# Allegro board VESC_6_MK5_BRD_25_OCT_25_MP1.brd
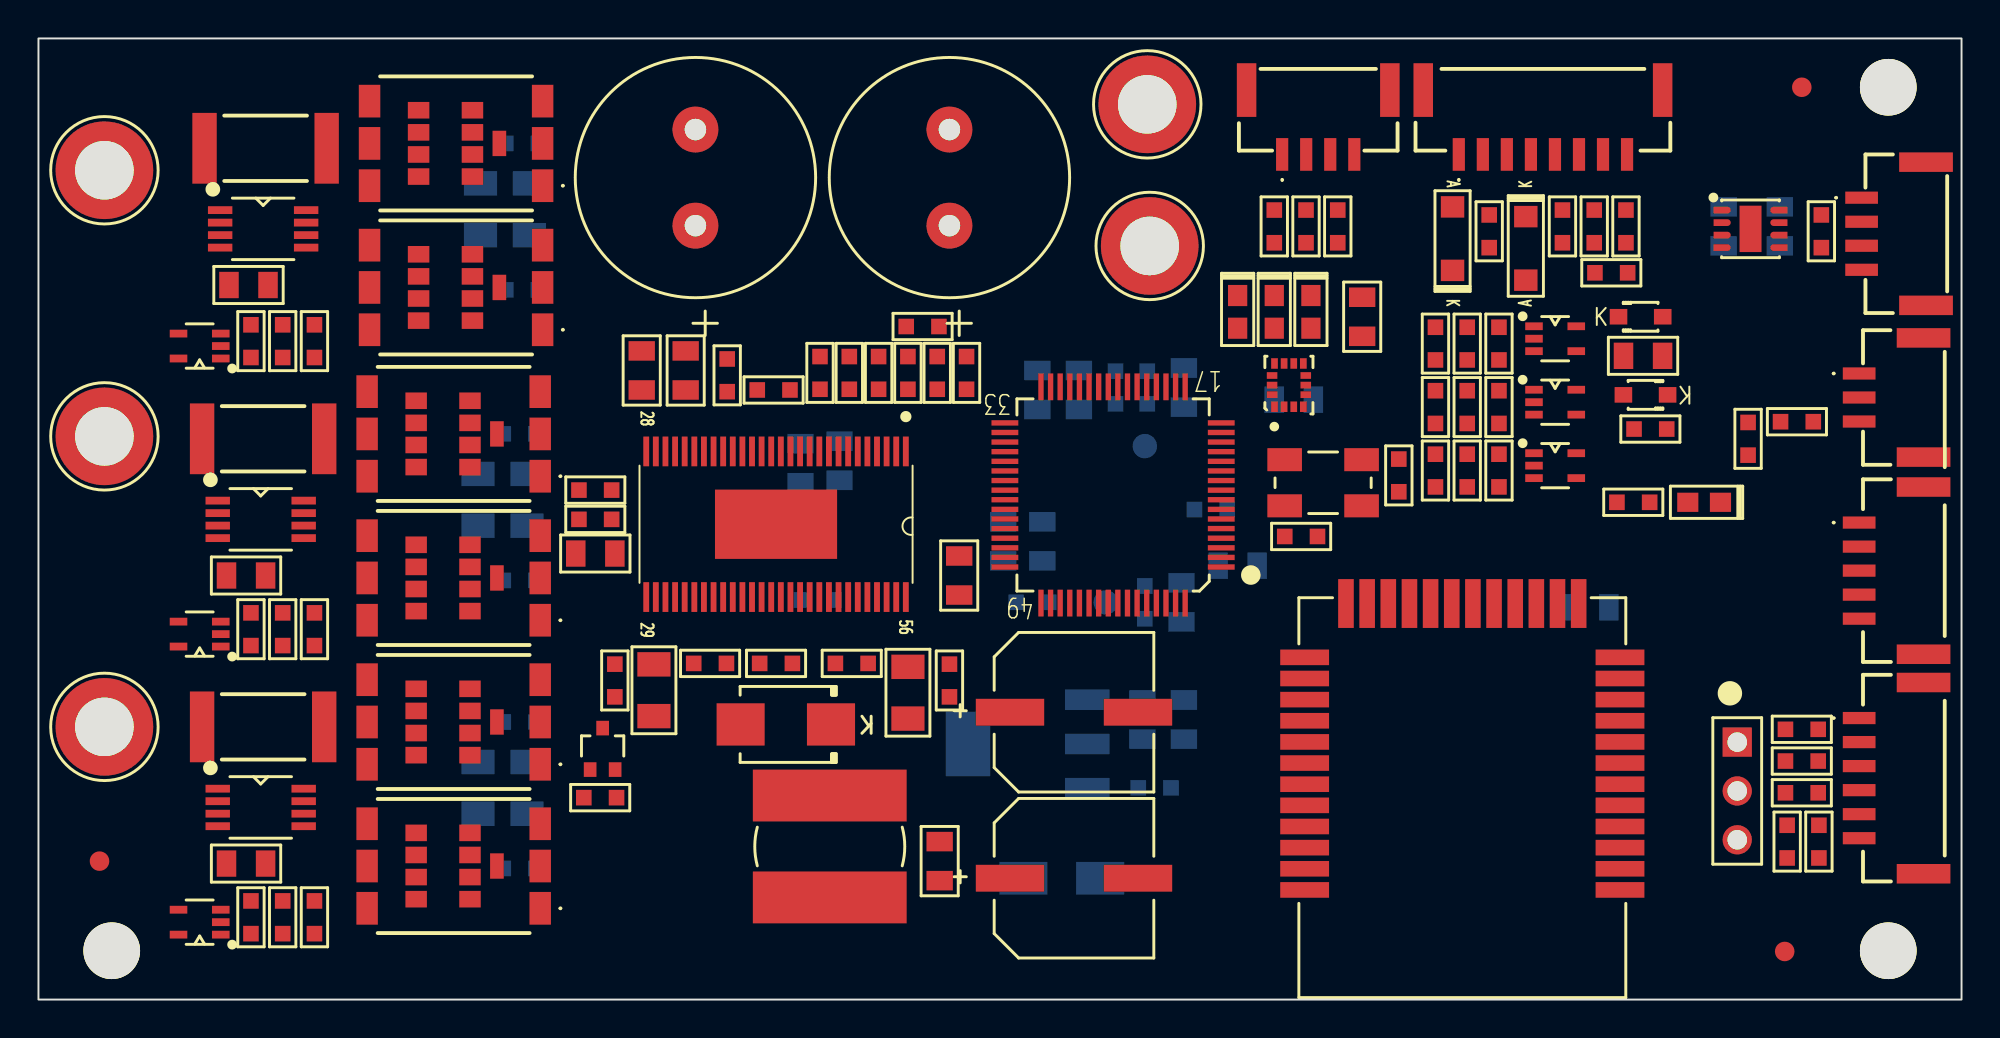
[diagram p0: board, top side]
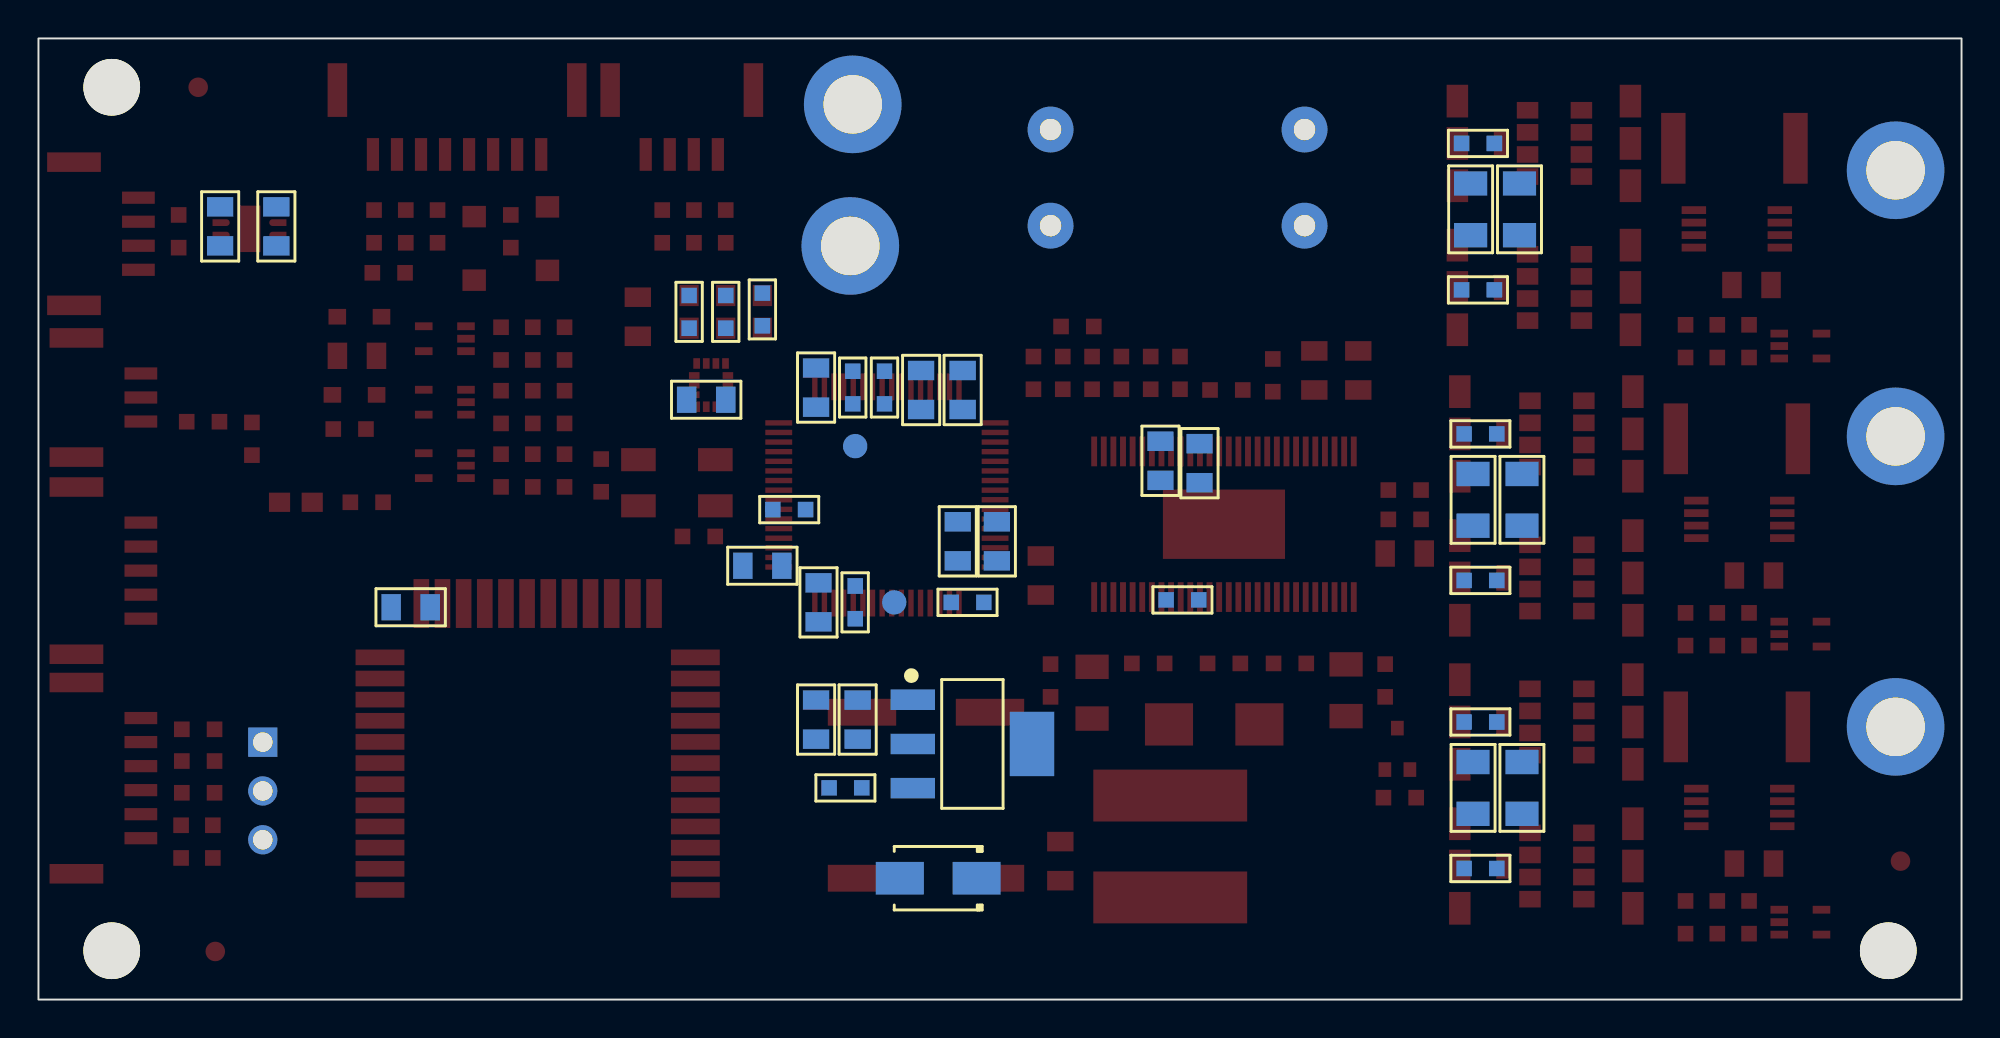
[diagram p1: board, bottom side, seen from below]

Outline 100 x 50 mm; copper layers: TOP, BOTTOM. Coordinates in mm from the lower left corner of the outline.
Outline path: rectangle 0,0 100,50

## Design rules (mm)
constraint set DEFAULT: min track width 0.203

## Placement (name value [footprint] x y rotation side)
C1  2.2uF  [0805]  83.44 33.49 0 top
C2  100nF  [0603]  79.25 40.22 90 top
C3  100nF  [0603]  92.58 8.22 270 top
C4  100nF  [0603]  88.9 29.17 90 top
C5  2.2uF  [0805]  68.83 35.52 90 top
C6  2.2uF  [0805]  65.28 31.2 180 bottom
C7  2.2uF  [0805]  90.55 40.22 90 bottom
C8  2.2uF  [0805]  87.63 40.22 90 bottom
C9  2.2uF  [0805]  80.65 20.41 180 bottom
C10  6.8nF  [0603]  45.97 35.01 0 top
C11  120pF  [0603]  46.74 32.6 90 top
C12  15nF  [0603]  47.37 16.6 90 top
C13  4.7uF_100V  [1206]  45.21 15.96 90 top
C14  100nF  [0603]  42.29 17.49 0 top
C15  220nF  [0603]  40.51 20.79 180 bottom
C16  2.2uF  [0805]  46.86 7.2 90 top
C17  47uF  [CAP_8X10]  53.85 14.95 0 top
C18  47uF  [CAP_8X10]  53.85 6.31 0 top
C19  22nF  [0603]  38.23 31.71 0 top
C20  220nF  [0603]  38.35 17.49 180 top
C21  2.2uF  [0805]  39.62 27.9 90 bottom
C22  2.2uF  [0805]  41.66 28.03 90 bottom
C23  220nF  [0603]  34.92 17.49 180 top
C24  2.2uF  [0805]  33.66 32.73 270 top
C25  2.2uF  [0805]  31.37 32.73 270 top
C26  4.7uF_100V  [1206]  32 16.09 90 top
C27  100nF  [0603]  75.95 27.52 90 top
C28  100nF  [0603]  75.95 30.82 90 top
C29  100nF  [0603]  75.95 34.13 90 top
C30  2.2u  [0603]  58.04 11.01 180 bottom
C31  2.2uF  [0805]  57.4 14.57 270 bottom
C32  2.2uF  [0805]  59.56 14.57 270 bottom
C33  4.7uF_100V  [1206]  22.99 41.11 90 bottom
C34  4.7uF_100V  [1206]  25.53 41.11 90 bottom
C35  4.7uF_100V  [1206]  22.86 26 90 bottom
C36  4.7uF_100V  [1206]  25.4 26 90 bottom
C37  4.7uF_100V  [1206]  25.4 11.01 90 bottom
C38  4.7uF_100V  [1206]  22.86 11.01 90 bottom
C39  2.2uF  [0805]  10.92 37.17 0 top
C40  2.2uF  [0805]  10.79 22.06 0 top
C41  2.2uF  [0805]  10.79 7.07 0 top
C42  1n  [0603]  12.7 34.25 90 top
C43  1n  [0603]  12.7 19.27 90 top
C44  1n  [0603]  12.7 4.28 90 top
C45  15nF  [0603]  11.05 34.25 90 top
C46  15nF  [0603]  11.05 19.27 90 top
C47  15nF  [0603]  11.05 4.28 90 top
C48  2.2uF  [0805]  28.96 23.2 180 top
C49  680uF_63V  [ECAP_TH_12P5X35MM]  34.16 42.76 90 top
C50  680uF_63V  [ECAP_TH_12P5X35MM]  47.37 42.76 90 top
C51  15PF  [0603]  70.74 27.27 90 top
C52  15PF  [0603]  65.66 24.09 180 top
C53  100nF  [0603]  60.96 25.49 0 bottom
C54  2.2uF  [0805]  59.44 20.66 90 bottom
C55  2.2uF  [0805]  52.2 23.84 270 bottom
C56  2.2uF  [0805]  50.16 23.84 90 bottom
C57  2.2uF  [0805]  62.36 22.57 0 bottom
C58  2.2uF  [0805]  59.56 31.84 270 bottom
C59  2.2uF  [0805]  51.94 31.71 270 bottom
C60  2.2uF  [0805]  54.1 31.71 90 bottom
C61  2.2uF  [0805]  47.88 22.06 270 top
D1  D_Schottky  [SOD_123]  73.53 39.59 270 top
D2  D_Schottky  [SOD_323]  83.31 35.52 0 top
D3  3.6V  [SOD_123]  77.34 39.08 90 top
D4  D_Schottky  [SOD_323]  83.57 31.46 180 top
D5  BLUE  [LED_0603]  66.17 35.78 90 top
D6  RED  [LED_0603]  62.36 35.78 90 top
D7  GREEN  [LED_0603]  64.26 35.78 90 top
D8  RED  [LED_0603]  86.61 25.87 0 top
D9  DIODE SCHOTTKY  [DO214AA]  38.86 14.31 180 top
D10  TVS_5V  [DO-214AC]  53.21 6.31 0 bottom
J3  DRV8301  [HTSSOP_56P_6X14MM]  38.35 24.73 270 top
J4  CON3  [HDR_1X3]  88.34 13.39 270 top
L1  22uH  [IND_7P8X7P8_SDR0805]  41.15 7.96 90 top
NOREF  -  [unnamed]  3.17 7.2 0 top
NOREF#2  -  [unnamed]  91.69 47.46 0 top
NOREF#3  -  [unnamed#2]  3.81 2.54 0 top
NOREF#4  -  [unnamed]  90.81 2.5 0 top
NOREF#5  -  [#3]  0 0 90 top
NOREF#6  -  [#3]  0 50 0 top
NOREF#7  -  [unnamed#2]  96.19 2.54 0 top
NOREF#8  -  [#3]  -1429.39 -1577.61 0 top
NOREF#9  -  [#3]  50.25 30 0 top
NOREF#10  -  [unnamed#2]  96.19 47.46 0 top
P1  SWD_VER  [CON_4P_VRT_BM04BGHSTB]  66.55 46.19 180 top
P2  HALL_ENC  [CON_6P_VRT_BM06BGHSTBT]  96.9 11.52 90 top
P3  COMM  [CON_8P_VRT_BM08BGHSTBT]  78.23 46.19 180 top
P4  SERVO  [CON_3P_VRT_BM03BGHSTB]  96.9 30.7 90 top
P5  SWD_VER  [CON_5P_VRT_BM05BGHSTBT]  96.9 22.31 90 top
P6  CAN  [CON_4P_VRT_BM04BGHSTB]  97.03 39.84 90 top
P7  SUPPLY  [TP_TH_120MILS]  57.78 39.21 0 top
P8  PH_A  [TP_TH_120MILS]  3.43 43.14 0 top
P9  PH_B  [TP_TH_120MILS]  3.43 29.3 0 top
P10  PH_C  [TP_TH_120MILS]  3.43 14.19 0 top
P11  GND  [TP_TH_120MILS]  57.66 46.57 0 top
Q1  DMN62D0UW-7  [SOT323_3P]  29.34 13.04 0 top
Q2  IRF7749  [IRF7749L1TRPBF]  21.72 37.05 180 top
Q3  IRF7749  [IRF7749L1TRPBF]  21.59 6.95 180 top
Q4  IRF7749  [IRF7749L1TRPBF]  21.59 21.93 180 top
Q5  IRF7749  [IRF7749L1TRPBF]  21.72 44.54 180 top
Q6  IRF7749  [IRF7749L1TRPBF]  21.59 29.43 180 top
Q7  IRF7749  [IRF7749L1TRPBF]  21.59 14.44 180 top
R1  0R,DNP  [0603]  64.26 40.22 270 top
R2  22R  [0603]  65.91 40.22 270 top
R3  22R  [0603]  67.56 40.22 270 top
R4  2k2  [0603]  91.69 10.76 0 top
R5  39k  [0603]  75.44 39.97 90 top
R6  2k2  [0603]  91.69 12.41 0 top
R7  2k2  [0603]  91.69 14.06 0 top
R8  10k  [0603]  90.93 8.22 270 top
R9  56k  [0603]  80.9 40.22 90 top
R10  220R  [0603]  83.82 29.68 0 top
R11  1k_PTC  [0603]  81.79 37.81 180 top
R12  1k_PTC  [0603]  82.55 40.22 270 top
R13  100R  [0603]  91.44 30.06 0 top
R14  1k  [0603]  66.17 35.78 270 bottom
R15  220R  [0603]  62.36 35.9 270 bottom
R16  220R  [0603]  64.26 35.78 270 bottom
R17  1k  [0603]  56.01 31.84 270 bottom
R18  1k  [0603]  51.69 20.66 180 bottom
R19  220R  [0603]  92.71 39.97 90 top
R20  1k  [0603]  82.93 25.87 180 top
R21  3.3k  [0603]  43.69 32.6 270 top
R22  220K  [0603]  48.26 32.6 270 top
R23  15k  [0603]  45.21 32.6 270 top
R24  18k  [0603]  42.16 32.6 90 top
R25  10k  [0603]  40.64 32.6 270 top
R26  10k  [0603]  35.81 32.47 270 top
R27  39k  [0603]  29.97 16.6 270 top
R28  2k2  [0603]  29.21 10.5 180 top
R29  39k_60V  [0603]  72.64 27.52 270 top
R30  39k_60V  [0603]  72.64 30.82 270 top
R31  39k_60V  [0603]  72.64 34.13 270 top
R32  2k2  [0603]  74.3 27.52 90 top
R33  2k2  [0603]  74.3 30.82 90 top
R34  2k2  [0603]  74.3 34.13 90 top
R35  4.7R  [0603]  25.02 21.81 180 bottom
R36  4.7R  [0603]  25.15 36.92 180 bottom
R37  4.7R  [0603]  25.02 6.82 180 bottom
R38  0.0005R  [2512]  11.81 44.29 0 top
R39  0.0005R  [2512]  11.68 29.17 0 top
R40  0.0005R  [2512]  11.68 14.19 0 top
R41  4.7R  [0603]  25.15 44.54 180 bottom
R42  4.7R  [0603]  25.02 29.43 180 bottom
R43  4.7R  [0603]  25.02 14.44 180 bottom
R44  1k  [0603]  14.35 34.25 90 top
R45  1k  [0603]  14.35 19.27 90 top
R46  1k  [0603]  14.35 4.28 90 top
R47  NTC_10K  [0603]  28.96 26.51 180 top
R48  10k  [0603]  28.96 24.98 0 top
R49  0R  [0603]  57.53 20.66 90 bottom
R50  0R  [0603]  57.66 31.84 270 bottom
TP1  T POINT R  [TP_50MIL]  57.53 28.79 0 bottom
TP2  T POINT R  [TP_50MIL]  55.5 20.66 0 bottom
U2  BMI270  [LGA_14P_2P5X3MM]  65.02 31.97 90 top
U3  TJA1051TK3  [VSON_8P_3X3MM_TP]  89.03 40.09 270 top
U4  Core51822(B)  [BLE_36P_MOD_17X20P8MM_NRF_CORE51822B]  74.04 10.5 180 top
U5  TC2117  [SOT223_4P]  51.43 13.3 180 bottom
U6  MC74VHC1GT66  [SC70_5P]  78.87 27.78 0 top
U7  MC74VHC1GT66  [SC70_5P]  78.87 31.08 0 top
U8  MC74VHC1GT66  [SC70_5P]  78.87 34.38 0 top
U9  AD8418  [MSOP8]  11.68 40.09 0 top
U10  AD8418  [MSOP8]  11.56 24.98 0 top
U11  AD8418  [MSOP8]  11.56 10 0 top
U12  MC74VHC1GT66  [SC70_5P]  8.38 34 180 top
U13  MC74VHC1GT66  [SC70_5P]  8.38 19.01 180 top
U14  MC74VHC1GT66  [SC70_5P]  8.38 4.03 180 top
U15  STM32F405RGT6_LQFP64  [LQFP64_10X10MM]  55.88 26.25 180 top
Y1  ABM3B-8.000MHZ  [XTAL_4P_5X3P2MM_ABM3B]  66.8 26.89 0 top

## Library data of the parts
C1-C16 C19-C48 C51-C61 = CAP NP
C17 C18 C49 C50 = CAP POL_0
D1 D2 D4 = DIODE SCHOTTKY_0
D3 = DIODE31_0
D5-D8 = LED_3
D9 = DIODE SCHOTTKY_1
D10 = DIODE TVS_0
J3 = CON58_3
J4 = CON3_1
L1 = INDUCTOR
P1 = CON6A_8
P2 = CON6_0
P3 = CON8
P4 = CON3
P5 = CON5
P6 = CON4_0
P7-P11 = CON1
Q1 = MOSFET N_3
Q2-Q7 = MOSFET N_5
R1-R37 R41-R50 = R
R38-R40 = R_3
TP1 TP2 = T POINT R
U2 = CON14C_1
U3 = CON8_8
U4 = CON28C_9
U5 = CON2AP_4
U6-U8 U12-U14 = CON6A_5
U9-U11 = CON8A_5
U15 = CON60_5
Y1 = CRYSTAL1-4/SM_9

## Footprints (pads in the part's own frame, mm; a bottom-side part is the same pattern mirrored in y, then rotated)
0603
  rect 0.813x0.813 smd: 1(-0.851,0) 2(0.851,0)
0805
  rect 1.016x1.372 smd: 1(-1.016,0) 2(1.016,0)
1206
  rect 1.27x1.727 smd: 1(-1.346,0) 2(1.346,0)
2512
  rect 1.27x3.683 smd: 1(-3.175,0) 2(3.175,0)
BLE_36P_MOD_17X20P8MM_NRF_CORE51822B
  rect 2.54x0.813 smd: 1(-8.2,4.8) 2(-8.2,3.7) 3(-8.2,2.6) 4(-8.2,1.5) 5(-8.2,0.4) 6(-8.2,-0.7) 7(-8.2,-1.8) 8(-8.2,-2.9) 9(-8.2,-4) 10(-8.2,-5.1) 11(-8.2,-6.2) 12(-8.2,-7.3) 25(8.2,-7.3) 26(8.2,-6.2) 27(8.2,-5.1) 28(8.2,-4) 29(8.2,-2.9) 30(8.2,-1.8) 31(8.2,-0.7) 32(8.2,0.4) 33(8.2,1.5) 34(8.2,2.6) 35(8.2,3.7) 36(8.2,4.8)
  rect 0.813x2.54 smd: 13(-6.05,-10.1) 14(-4.95,-10.1) 15(-3.85,-10.1) 16(-2.75,-10.1) 17(-1.65,-10.1) 18(-0.55,-10.1) 19(0.55,-10.1) 20(1.65,-10.1) 21(2.75,-10.1) 22(3.85,-10.1) 23(4.95,-10.1) 24(6.05,-10.1)
CAP_8X10
  rect 3.556x1.397 smd: N(3.328,0) P(-3.328,0)
CON_3P_VRT_BM03BGHSTB
  rect 1.016x2.794 smd: (-2.475,-1.125) (3.725,-1.125)
  rect 0.635x1.702 smd: 1(1.875,2.225) 2(0.625,2.225) 3(-0.625,2.225)
CON_4P_VRT_BM04BGHSTB
  rect 1.016x2.794 smd: (-3.725,-1.125) (3.725,-1.125)
  rect 0.635x1.702 smd: 1(1.875,2.225) 2(0.625,2.225) 3(-0.625,2.225) 4(-1.875,2.225)
CON_5P_VRT_BM05BGHSTBT
  rect 1.016x2.794 smd: (-4.35,-1.125) (4.35,-1.125)
  rect 0.635x1.702 smd: 1(2.5,2.225) 2(1.25,2.225) 3(0,2.225) 4(-1.25,2.225) 5(-2.5,2.225)
CON_6P_VRT_BM06BGHSTBT
  rect 1.016x2.794 smd: (-4.975,-1.125) (4.975,-1.125)
  rect 0.635x1.702 smd: 1(3.125,2.225) 2(1.875,2.225) 3(0.625,2.225) 4(-0.625,2.225) 5(-1.875,2.225) 6(-3.125,2.225)
CON_8P_VRT_BM08BGHSTBT
  rect 1.016x2.794 smd: (-6.225,-1.125) (6.225,-1.125)
  rect 0.635x1.702 smd: 1(4.375,2.225) 2(3.125,2.225) 3(1.875,2.225) 4(0.625,2.225) 5(-0.625,2.225) 6(-1.875,2.225) 7(-3.125,2.225) 8(-4.375,2.225)
DO214AA
  rect 2.5x2.2 smd: A(2.35,0) K(-2.35,0)
DO-214AC
  rect 2.5x1.7 smd: A(2,0) K(-2,0)
ECAP_TH_12P5X35MM
  round 2.388 hole 1.118: N(2.5,0) P(-2.5,0)
HDR_1X3
  rect 1.524x1.524 hole 1.016: 1(0,0)
  round 1.524 hole 1.016: 2(2.54,0) 3(5.08,0)
HTSSOP_56P_6X14MM
  rect 1.549x0.305 smd: 1(-3.788,6.75) 2(-3.788,6.25) 3(-3.788,5.75) 4(-3.788,5.25) 5(-3.788,4.75) 6(-3.788,4.25) 7(-3.788,3.75) 8(-3.788,3.25) 9(-3.788,2.75) 10(-3.788,2.25) 11(-3.788,1.75) 12(-3.788,1.25) 13(-3.788,0.75) 14(-3.788,0.25) 15(-3.788,-0.25) 16(-3.788,-0.75) 17(-3.788,-1.25) 18(-3.788,-1.75) 19(-3.788,-2.25) 20(-3.788,-2.75) 21(-3.788,-3.25) 22(-3.788,-3.75) 23(-3.788,-4.25) 24(-3.788,-4.75) 25(-3.788,-5.25) 26(-3.788,-5.75) 27(-3.788,-6.25) 28(-3.788,-6.75) 29(3.788,-6.75) 30(3.788,-6.25) 31(3.788,-5.75) 32(3.788,-5.25) 33(3.788,-4.75) 34(3.788,-4.25) 35(3.788,-3.75) 36(3.788,-3.25) 37(3.788,-2.75) 38(3.788,-2.25) 39(3.788,-1.75) 40(3.788,-1.25) 41(3.788,-0.75) 42(3.788,-0.25) 43(3.788,0.25) 44(3.788,0.75) 45(3.788,1.25) 46(3.788,1.75) 47(3.788,2.25) 48(3.788,2.75) 49(3.788,3.25) 50(3.788,3.75) 51(3.788,4.25) 52(3.788,4.75) 53(3.788,5.25) 54(3.788,5.75) 55(3.788,6.25) 56(3.788,6.75)
  rect 3.607x6.35 smd: 57(0,0)
IND_7P8X7P8_SDR0805
  rect 2.7x8 smd: 1(-2.65,0) 2(2.65,0)
IRF7749L1TRPBF
  rect 1.118x1.702 smd: 1(-4.5,2.2) 2(-4.5,0) 3(-4.5,-2.2) 4(4.5,-2.2) 5(4.5,0) 6(4.5,2.2)
  rect 0.711x1.321 smd: 7(-2.25,0)
  rect 1.118x0.864 smd: 8(-0.85,1.725) 9(-0.85,0.575) 10(-0.85,-0.575) 11(-0.85,-1.725) 12(1.95,-1.725) 13(1.95,-0.575) 14(1.95,0.575) 15(1.95,1.725)
LED_0603
  rect 1.1x1 smd: A(-0.85,0) K(0.85,0)
LGA_14P_2P5X3MM
  rect 0.55x0.35 smd: 1(-1.125,0.75) 2(-1.125,0.25) 3(-1.125,-0.25) 4(-1.125,-0.75) 8(1.125,-0.75) 9(1.125,-0.25) 10(1.125,0.25) 11(1.125,0.75)
  rect 0.35x0.55 smd: 5(-0.5,-0.875) 6(0,-0.875) 7(0.5,-0.875) 12(0.5,0.875) 13(0,0.875) 14(-0.5,0.875)
LQFP64_10X10MM
  rect 1.397x0.279 smd: 1(-5.625,3.749) 2(-5.625,3.251) 3(-5.625,2.751) 4(-5.625,2.25) 5(-5.625,1.75) 6(-5.625,1.25) 7(-5.625,0.749) 8(-5.625,0.249) 9(-5.625,-0.249) 10(-5.625,-0.749) 11(-5.625,-1.25) 12(-5.625,-1.75) 13(-5.625,-2.25) 14(-5.625,-2.751) 15(-5.625,-3.251) 16(-5.625,-3.749) 33(5.625,-3.749) 34(5.625,-3.251) 35(5.625,-2.751) 36(5.625,-2.25) 37(5.625,-1.75) 38(5.625,-1.25) 39(5.625,-0.749) 40(5.625,-0.249) 41(5.625,0.249) 42(5.625,0.749) 43(5.625,1.25) 44(5.625,1.75) 45(5.625,2.25) 46(5.625,2.751) 47(5.625,3.251) 48(5.625,3.749)
  rect 0.279x1.397 smd: 17(-3.749,-5.625) 18(-3.251,-5.625) 19(-2.751,-5.625) 20(-2.25,-5.625) 21(-1.75,-5.625) 22(-1.25,-5.625) 23(-0.749,-5.625) 24(-0.249,-5.625) 25(0.249,-5.625) 26(0.749,-5.625) 27(1.25,-5.625) 28(1.75,-5.625) 29(2.25,-5.625) 30(2.751,-5.625) 31(3.251,-5.625) 32(3.749,-5.625) 49(3.749,5.625) 50(3.251,5.625) 51(2.751,5.625) 52(2.25,5.625) 53(1.75,5.625) 54(1.25,5.625) 55(0.749,5.625) 56(0.249,5.625) 57(-0.249,5.625) 58(-0.749,5.625) 59(-1.25,5.625) 60(-1.75,5.625) 61(-2.25,5.625) 62(-2.751,5.625) 63(-3.251,5.625) 64(-3.749,5.625)
MSOP8
  rect 1.27x0.406 smd: 1(-2.235,0.975) 2(-2.235,0.325) 3(-2.235,-0.325) 4(-2.235,-0.975) 5(2.235,-0.975) 6(2.235,-0.325) 7(2.235,0.325) 8(2.235,0.975)
SC70_5P
  rect 0.914x0.406 smd: 1(-1.098,0.648) 2(-1.098,0) 3(-1.098,-0.648) 4(1.098,-0.648) 5(1.098,0.648)
SOD_123
  rect 1.118x1.219 smd: A(-1.652,0) K(1.652,0)
SOD_323
  rect 0.914x0.813 smd: A(1.15,0) K(-1.15,0)
SOT223_4P
  rect 2.311x1.067 smd: 1(-3.1,2.3) 2(-3.1,0) 3(-3.1,-2.3)
  rect 2.311x3.353 smd: 4(3.1,0)
SOT323_3P
  rect 0.66x0.762 smd: 1(-0.65,-1.078) 2(0.65,-1.078) 3(0,1.078)
TP_50MIL
  round 1.27 smd: 1(0,0)
TP_TH_120MILS
  round 5.08 hole 3.048: 1(0,0)
unnamed
  round 1.016 smd: 1(0,0)
unnamed#2
  round 2.946 hole 3.2 unplated: (0,0)
VSON_8P_3X3MM_TP
  custom 0.088x0.088 smd: 1(-0.975,-1.475) 2(-0.325,-1.475) 3(0.325,-1.475) 4(0.975,-1.475) 5(0.975,1.475) 6(0.325,1.475) 7(-0.325,1.475) 8(-0.975,1.475)
  rect 2.413x1.143 smd: 9(0,0)
XTAL_4P_5X3P2MM_ABM3B
  rect 1.8x1.2 smd: 1(-2,-1.2) 2(2,-1.2) 3(2,1.2) 4(-2,1.2)

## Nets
+5V: C8.1 C16.1 C17.P C18.P C30.2 D10.K(CATHODE) J4.1 L1.1 P3.1 P4.2 P6.4 Q1.1 R1.2 R24.2 U3.3 U5.3(VI)
VCC: C5.1 C6.1 C7.1 C9.2 C31.2 C32.2 C39.2 C40.2 C41.2 C54.2 C55.2 C56.1 C57.2 C58.2 C59.2 D5.A J3.49 J4.3 P3.2 P5.5 R8.2 R17.2 R18.2 R47.2 U2.5(VDDIO) U2.8 U2.12 U3.5(VIO) U4.12(VCC) U5.2 U5.4 U6.5(VCC) U7.5(VCC) U8.5(VCC) U9.6(VS) U9.7 U10.6(VS) U10.7 U11.6(VS) U11.7 U12.5(VCC) U13.5(VCC) U14.5(VCC) U15.1 U15.13 U15.19 U15.32 U15.48 U15.64
0: C1.1 C2.1 C3.2 C4.1 C5.2 C6.2 C7.2 C8.2 C9.1 C10.2 C11.2 C12.1 C13.1 C16.2 C17.N C18.N C21.1 C22.1 C24.1 C25.1 C26.1 C30.1 C31.1 C32.1 C51.1 C52.1 C53.1 C54.1 C55.1 C56.2 C57.1 C58.1 C59.1 C60.2 C61.2 D3.A D4.A D8.K(CATHODE) D9.A D10.A J3.28 J3.30 J3.31 J3.32 J3.33 J3.57 P1.4 P2.1 P3.3 P4.1 P5.3 P6.1 R14.2 R15.2 R16.2 R21.1 R22.1 R25.1 R26.1 R28.2 R32.2 R33.2 R34.2 R49.1 U2.1 U2.6 U2.7 U3.2 U3.8 U3.9 U4.1 U4.11 U5.1 U6.2 U6.3 U7.2 U7.3 U8.2 U8.3 U15.12 U15.18 U15.63(VSS_2) Y1.2 Y1.4
BT_HV: C13.2 C26.2 C33.1 C34.1 C35.1 C36.1 C37.1 C38.1 C49.P C50.P J3.29 J3.53 J3.54 P7.1 Q2.1 Q2.2 Q2.3 Q2.4 Q2.5 Q2.6 Q3.1 Q3.2 Q3.3 Q3.4 Q3.5 Q3.6 Q4.1 Q4.2 Q4.3 Q4.4 Q4.5 Q4.6 R27.1
C_A: R44.2 U9.5
C_B: R45.2 U10.5
C_C: R46.2 U11.5
CONN_SW: P3.8 R12.1
EN_BUCK: C2.2 D3.K J3.55 R5.2 R9.2
PH_A: P8.1 R38.1 U9.1
PH_B: P9.1 R39.1 U10.1
PH_C: P10.1 R40.1 U11.1
SH_A: C15.2 D1.A J3.46 Q2.8 Q2.9 Q2.10 Q2.11 Q2.12 Q2.13 Q2.14 Q2.15(S8) Q5.1 Q5.2 Q5.3 Q5.4 Q5.5 Q5.6 R29.1 R38.2 U9.8
SHUTDOWN: R10.1 U15.25
N113958: J4.2 P2.6 R4.1 R6.1 R7.1
N114102: P2.2 R7.2 U15.39
N114106: P2.3 R6.2 U15.38
N114110: P2.4 R4.2 U15.37
N114114: C3.1 P2.5 R8.1 U15.24
N119424: P4.3 R13.2
N119428: C4.2 R13.1 U15.58
N316048: P5.4 U15.49
N316068: P5.2 U15.46
N316080: C53.2 P5.1 U15.7
N316972: D5.K(CATHODE) R14.1
N317032: D6.A U15.27
N317036: D6.K(CATHODE) R15.1
N317096: D7.A U15.26
N317100: D7.K(CATHODE) R16.1
N320425: D2.K(CATHODE) R9.1 R11.2
N320494: R11.1 R12.2
N320696: C1.2 D2.A D4.K(CATHODE) R10.2
N321457: D1.K(CATHODE) R5.1
N379550: C60.1 U15.31
N379578: C61.1 U15.47
N382210: C12.2 J3.56
N382270: C10.1 R23.1
N382306: J3.3(VSENSE) R21.2 R24.1
N382374: C11.1 J3.2 R23.2
N382386: J3.1 R22.2
N382652: C14.2 J3.52
N382656: C14.1 D9.K(CATHODE) J3.50 J3.51 L1.2
N382740: J3.7 R25.2
N382848: C15.1 J3.48
N382956: C21.2 C22.2 J3.13
N383040: C19.2 J3.14
N383044: C20.1 J3.43
N383064: C19.1 J3.15
N383228: C23.1 J3.38
N383264: Q1.3 R27.2
N383316: C24.2 J3.23
N383358: C25.2 J3.24 J3.27
N399081: Q5.7 R41.2
N399151: Q2.7 R36.2
N405714: Q4.7 R35.2
N405958: Q6.7 R42.2
N406713: Q3.7 R37.2
N406957: Q7.7 R43.2
N413411: C45.1 U12.2
N415177: C46.1 U13.2
N415727: C47.1 U14.2
N421403: P1.1(VBUS) R1.1
N421435: P1.2 R2.1
N421455: R2.2 U15.44
N421467: P1.3 R3.1
N421471: R3.2 U15.45
N440238: C52.2 U15.5 Y1.1
N440256: C51.2 U15.6 Y1.3
N453854: C27.2 U6.1
N453874: C28.2 U7.1
N453894: C29.2 U8.1
N475951: R49.2 TP2.1(TP) U15.60
N476249: R50.2 TP1.1(TP) U15.28
N483635: J3.47 R36.1
N483651: J3.45 R41.1
N483659: C33.2 C34.2 C35.2 C36.2 C37.2 C38.2 C39.1 C40.1 C41.1 C42.2 C43.2 C44.2 C45.2 C46.2 C47.2 C48.2 C49.N C50.N J3.34 J3.39 J3.44 P11.1 Q5.8 Q5.9 Q5.10 Q5.11 Q5.12 Q5.13 Q5.14 Q5.15(S8) Q6.8 Q6.9 Q6.10 Q6.11 Q6.12 Q6.13 Q6.14 Q6.15(S8) Q7.8 Q7.9 Q7.10 Q7.11 Q7.12 Q7.13 Q7.14 Q7.15(S8) R48.1 U9.2 U9.3 U10.2 U10.3 U11.2 U11.3 U12.3 U13.3 U14.3
N488558: P6.3 R19.2 U3.7
N488562: P6.2 R19.1 U3.6
N488738: R18.1 U2.13 U15.50
N488742: R17.1 R50.1 U2.14
N490262: U3.1 U15.62
N490274: U3.4 U15.61
N490496: U4.32 U15.20
N490506: U4.31 U15.33
N490510: U4.15 U15.52
N490514: U4.16 U15.53
N490522: R20.2 U4.17
N492162: P3.7 U15.22
N492166: P3.6 U15.23 U15.29
N492170: P3.5 U15.30
N492258: P3.4 U15.21
N494356: J3.17 U15.41
N494360: J3.19 U15.42
N494364: J3.21 U15.43
N494368: J3.18 U15.34
N494372: J3.20 U15.35
N494376: J3.22 U15.36
N494756: J3.6 U15.59
N494760: J3.16 R26.2 U15.57
N495156: J3.10 U15.55
N495160: J3.9 U15.56
N495164: J3.11 U15.51
N495168: J3.8 U15.40
N495709: C27.1 R29.2 R32.1 U15.14
N495713: C28.1 R30.2 R33.1 U15.15
N495717: C29.1 R31.2 R34.1 U15.16
N495721: Q1.2(S) R28.1 U15.11
N495725: U6.4 U7.4 U8.4 U15.2
N495729: U12.4 U13.4 U14.4 U15.54
N495741: C42.1 R44.1 U12.1 U15.8
N495753: C43.1 R45.1 U13.1 U15.9
N495765: C44.1 R46.1 U14.1 U15.10
N495777: C48.1 R47.1 R48.2 U15.17
N496269: J3.42 R35.1
N496273: C20.2 J3.41 Q4.8 Q4.9 Q4.10 Q4.11 Q4.12 Q4.13 Q4.14 Q4.15(S8) Q6.1 Q6.3 Q6.4 Q6.5 Q6.6 R30.1 R39.2 U10.8
N496277: J3.40 R42.1
N496285: J3.37 R37.1
N496289: C23.2 J3.36 Q3.8 Q3.9 Q3.10 Q3.11 Q3.12 Q3.13 Q3.14 Q3.15(S8) Q7.1 Q7.2 Q7.3 Q7.4 Q7.5 Q7.6 R31.1 R40.2 U11.8
N496293: J3.35 R43.1
N4906060: D8.A R20.1

Pads without a net: J3 4 5 12 25 26; NOREF 1; NOREF#2 1; NOREF#4 1; Q6 2; U2 2 3 4 9 10 11; U4 2 3 4 5 6 7 8 9 10 13 14 18 19 20 21 22 23 24 25 26 27 28 29 30 33 34 35 36; U9 4; U10 4; U11 4; U15 3 4

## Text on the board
User.9: NOTES : | 1.BASE MATERIAL : FR4 | 2.FLAMMABILITY : UL 94V-0 | 3.SURFACE : ENIG | 4.SOLDER MASK : GREEN | 5.SILKSCREEN COLOR : WHITE | 6.MANUFACTURE LOGO : NO | 2 LAYER STACKUP
User.38: 1.6 MM | +/-10 % | 1.0 OZ | LAYER 1 TOP | LAYER 2 BOTTOM | LAYER
User.45: FIGURE | FINISHED_SIZE | 12.0 | 144.0 | DRILL CHART: TOP to BOTTOM | ALL UNITS ARE IN MILS | TOLERANCE_DRILL | +3.0/-12.0 | +2.0/-2.0 | PLATED | NON-PLATED | QTY | 205 | 4
